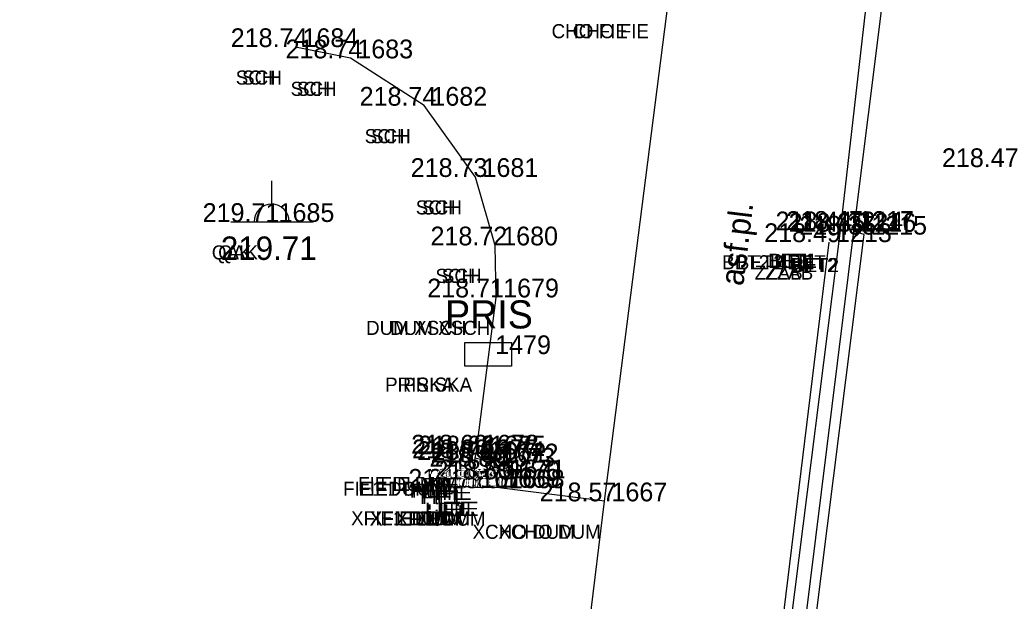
# Model space of a CAD drawing. Extents: x -471047 to -470889, y -1102859 to -1102000.
# Drawn here: x -470984.24 to -470963.12, y -1102410.26 to -1102397.86 of the extents above; entities that cross this region are included whole.
import ezdxf

# ---------------------------------------------------------------- set-up
doc = ezdxf.new("R2010")
doc.units = 0
for name, color, linetype in [('Vrstva 1', 7, 'Continuous'), ('Vrstva 10', 7, 'Continuous'), ('Vrstva 13', 7, 'Continuous'), ('Vrstva 17', 7, 'Continuous'), ('Vrstva 2', 7, 'Continuous'), ('Vrstva 22', 7, 'Continuous'), ('Vrstva 23', 7, 'Continuous'), ('Vrstva 34', 7, 'Continuous'), ('Vrstva 35', 7, 'Continuous'), ('Vrstva 36', 7, 'Continuous'), ('Vrstva 38', 7, 'Continuous'), ('Vrstva 5', 7, 'Continuous'), ('Vrstva 7', 7, 'Continuous'), ('Vrstva 8', 7, 'Continuous')]:
    doc.layers.add(name, color=color, linetype=linetype)

msp = doc.modelspace()

# ---------------------------------------------------------------- linework, layer by layer
at = {"layer": 'Vrstva 1'}
for points in [[(-471040.344, -1102858.385), (-471031.676, -1102846.187), (-471026.357, -1102838.629), (-471023.212, -1102833.975), (-471019.21, -1102827.465), (-471016.861, -1102823.272), (-471013.099, -1102815.912), (-471010.824, -1102810.955), (-471007.329, -1102802.292), (-471005.34, -1102796.515), (-471002.842, -1102787.838), (-471001.3, -1102780.997), (-471000.19, -1102774.713), (-470999.247, -1102768.204), (-470998.794, -1102764.784), (-470997.199, -1102751.812), (-470994.899, -1102732.807), (-470992.551, -1102713.262), (-470990.326, -1102694.887), (-470988.122, -1102676.57), (-470985.812, -1102657.305), (-470983.537, -1102638.407), (-470981.386, -1102620.622), (-470979.843, -1102608.014), (-470976.377, -1102579.253), (-470972.945, -1102550.69), (-470970.475, -1102530.206), (-470967.905, -1102508.801), (-470965.053, -1102485.131), (-470962.734, -1102465.9), (-470960.173, -1102444.812), (-470957.795, -1102425.103), (-470954.965, -1102401.839), (-470953.834, -1102392.574), (-470952.33, -1102379.985), (-470950.744, -1102366.853), (-470948.978, -1102352.106), (-470947.037, -1102335.844), (-470944.949, -1102318.462), (-470944.013, -1102310.745), (-470942.39, -1102297.267), (-470939.519, -1102273.45), (-470937.593, -1102257.43), (-470936.064, -1102244.81), (-470934.114, -1102228.634), (-470931.621, -1102207.856), (-470929.536, -1102190.857), (-470926.572, -1102166.31), (-470924.91, -1102152.663), (-470923.413, -1102140.333), (-470921.923, -1102127.669), (-470921.155, -1102120.084), (-470920.446, -1102109.574), (-470919.912, -1102099.137), (-470919.63, -1102088.981), (-470919.523, -1102081.193), (-470919.563, -1102070.395), (-470919.714, -1102064.236), (-470920.134, -1102054.704), (-470920.462, -1102047.615), (-470920.599, -1102044.52), (-470920.743, -1102041.873), (-470921.125, -1102034.455), (-470921.774, -1102030.337), (-470922.418, -1102027.787), (-470923.734, -1102023.93), (-470924.872, -1102021.434), (-470926.752, -1102018.182), (-470927.953, -1102016.45), (-470929.616, -1102014.424), (-470932.252, -1102011.756), (-470935.111, -1102009.425), (-470938.391, -1102007.371), (-470942.651, -1102005.401)], [(-471041.328, -1102857.18), (-471032.144, -1102844.242), (-471027.583, -1102837.763), (-471024.388, -1102833.028), (-471020.451, -1102826.6), (-471018.089, -1102822.378), (-471014.542, -1102815.445), (-471012.233, -1102810.418), (-471009.247, -1102803.108), (-471006.795, -1102796.098), (-471004.315, -1102787.532), (-471002.782, -1102780.723), (-471001.674, -1102774.458), (-471000.75, -1102768.095), (-471000.28, -1102764.601), (-470998.692, -1102751.741), (-470996.378, -1102732.635), (-470994.028, -1102713.058), (-470991.808, -1102694.749), (-470989.616, -1102676.447), (-470987.284, -1102657.013), (-470985.031, -1102638.272), (-470982.87, -1102620.431), (-470981.334, -1102607.933), (-470977.881, -1102579.263), (-470974.429, -1102550.492), (-470971.964, -1102530.054), (-470969.391, -1102508.607), (-470966.54, -1102484.984), (-470964.231, -1102465.853), (-470961.679, -1102444.752), (-470959.304, -1102425.078), (-470956.455, -1102401.634), (-470955.339, -1102392.489), (-470953.812, -1102379.71), (-470952.249, -1102366.808), (-470950.479, -1102352.023), (-470948.536, -1102335.868), (-470946.426, -1102318.233), (-470945.493, -1102310.531), (-470943.864, -1102297.013), (-470940.984, -1102273.071), (-470939.078, -1102257.195), (-470937.559, -1102244.684), (-470935.592, -1102228.353), (-470933.101, -1102207.653), (-470931.011, -1102190.57), (-470928.046, -1102166.021), (-470926.409, -1102152.578), (-470924.898, -1102140.121), (-470923.427, -1102127.544), (-470922.647, -1102119.826), (-470921.919, -1102109.229), (-470921.42, -1102099.134), (-470921.127, -1102089.016), (-470921.023, -1102081.453), (-470921.061, -1102070.468), (-470921.209, -1102064.314), (-470921.666, -1102053.966), (-470922.156, -1102043.345), (-470922.299, -1102039.934), (-470922.637, -1102034.36), (-470923.091, -1102031.241), (-470923.847, -1102028.247), (-470925.083, -1102024.594), (-470926.222, -1102022.086), (-470928.04, -1102018.943), (-470929.138, -1102017.357), (-470930.929, -1102015.175), (-470933.062, -1102013.049), (-470936.379, -1102010.368), (-470939.169, -1102008.662), (-470942.899, -1102006.906), (-470945.661, -1102005.908)], [(-471043.557, -1102855.955), (-471035.129, -1102844.026), (-471029.872, -1102836.499), (-471026.577, -1102831.578), (-471022.675, -1102825.415), (-471020.123, -1102821.053), (-471016.667, -1102814.59), (-471014.208, -1102809.45), (-471011.177, -1102802.451), (-471008.55, -1102795.333), (-471006.082, -1102787.209), (-471004.464, -1102780.376), (-471003.265, -1102774.167), (-471002.327, -1102767.948), (-471001.636, -1102762.527), (-471000.297, -1102751.605), (-470997.959, -1102732.524), (-470995.602, -1102712.802), (-470993.412, -1102694.623), (-470991.21, -1102676.17), (-470988.891, -1102656.857), (-470986.625, -1102638.083), (-470984.455, -1102620.195), (-470982.936, -1102607.733), (-470979.497, -1102579.223), (-470976.023, -1102550.279), (-470973.554, -1102529.822), (-470970.991, -1102508.497), (-470968.146, -1102484.787), (-470965.835, -1102465.72), (-470963.284, -1102444.529), (-470960.91, -1102424.942), (-470958.043, -1102401.343), (-470956.946, -1102392.356), (-470955.396, -1102379.408), (-470953.851, -1102366.636), (-470952.049, -1102351.733), (-470950.124, -1102335.611), (-470948.034, -1102318.083), (-470947.094, -1102310.328), (-470945.421, -1102296.51), (-470942.58, -1102272.848), (-470940.675, -1102256.948), (-470939.176, -1102244.526), (-470937.187, -1102228.174), (-470934.708, -1102207.467), (-470932.621, -1102190.433), (-470929.634, -1102165.778), (-470928.004, -1102152.415), (-470926.45, -1102139.595), (-470925.003, -1102127.418), (-470924.249, -1102119.695), (-470923.515, -1102109.093), (-470923.018, -1102099.069), (-470922.711, -1102088.911), (-470922.643, -1102081.356), (-470922.797, -1102070.414), (-470923.018, -1102064.454), (-470923.52, -1102053.203), (-470923.823, -1102047.529), (-470924.123, -1102041.506), (-470924.462, -1102037.486), (-470924.934, -1102031.904), (-470925.664, -1102028.672), (-470926.771, -1102025.506), (-470927.959, -1102022.914), (-470929.674, -1102020.028), (-470930.76, -1102018.498), (-470932.447, -1102016.478), (-470935.215, -1102013.816), (-470937.644, -1102011.98), (-470940.381, -1102010.371), (-470943.968, -1102008.669), (-470947.145, -1102007.524), (-470950.874, -1102006.74)], [(-471044.756, -1102855.056), (-471036.376, -1102843.177), (-471031.167, -1102835.741), (-471027.859, -1102830.8), (-471023.934, -1102824.593), (-471021.43, -1102820.312), (-471018.011, -1102813.91), (-471015.536, -1102808.75), (-471012.578, -1102801.897), (-471009.95, -1102794.77), (-471007.561, -1102786.914), (-471005.936, -1102780.074), (-471004.727, -1102773.818), (-471003.828, -1102767.827), (-471003.121, -1102762.345), (-471001.787, -1102751.467), (-470999.446, -1102732.348), (-470997.073, -1102712.539), (-470994.902, -1102694.521), (-470992.696, -1102676.023), (-470990.376, -1102656.68), (-470988.131, -1102638.071), (-470985.947, -1102620.018), (-470984.417, -1102607.512), (-470980.993, -1102579.08), (-470977.514, -1102550.137), (-470975.048, -1102529.649), (-470972.488, -1102508.37), (-470969.618, -1102484.508), (-470967.34, -1102465.669), (-470964.767, -1102444.39), (-470962.402, -1102424.781), (-470959.534, -1102401.193), (-470958.432, -1102392.151), (-470956.883, -1102379.208), (-470955.335, -1102366.424), (-470953.535, -1102351.506), (-470951.606, -1102335.399), (-470949.519, -1102317.94), (-470948.575, -1102310.159), (-470946.889, -1102296.144), (-470944.056, -1102272.618), (-470942.139, -1102256.659), (-470940.657, -1102244.341), (-470938.638, -1102227.749), (-470936.19, -1102207.298), (-470934.102, -1102190.255), (-470931.124, -1102165.639), (-470929.492, -1102152.254), (-470927.915, -1102139.252), (-470926.46, -1102127.103), (-470925.74, -1102119.604), (-470925.012, -1102108.913), (-470924.523, -1102099.054), (-470924.217, -1102088.866), (-470924.148, -1102081.334), (-470924.301, -1102070.391), (-470924.518, -1102064.43), (-470924.97, -1102054.435), (-470925.588, -1102041.569), (-470925.963, -1102035.313), (-470926.405, -1102032.225), (-470927.078, -1102029.198), (-470928.123, -1102026.148), (-470929.318, -1102023.558), (-470930.84, -1102020.97), (-470931.868, -1102019.515), (-470933.443, -1102017.605), (-470936.26, -1102014.885), (-470938.429, -1102013.255), (-470941.213, -1102011.639), (-470944.847, -1102009.927), (-470947.723, -1102008.912), (-470951.444, -1102008.161), (-470954.511, -1102007.931), (-470957.895, -1102008.041)]]:
    msp.add_spline(points, degree=3, dxfattribs=at)
at = {"layer": 'Vrstva 10'}
for p, q in [((-470974.508, -1102407.105), (-470974.083, -1102403.784)), ((-470974.568, -1102407.837), (-470974.525, -1102407.212)), ((-470974.525, -1102407.212), (-470974.508, -1102407.105)), ((-470974.062, -1102407.837), (-470974.568, -1102407.837)), ((-470973.962, -1102407.851), (-470974.062, -1102407.837)), ((-470971.771, -1102408.129), (-470973.962, -1102407.851)), ((-470972.725, -1102415.976), (-470971.771, -1102408.129))]:
    msp.add_line(p, q, dxfattribs=at)
at = {"layer": 'Vrstva 13'}
for p, q in [((-470978.867, -1102401.792), (-470978.867, -1102401.292)), ((-470978.867, -1102401.792), (-470978.867, -1102402.167)), ((-470978.867, -1102401.817), (-470978.867, -1102401.817)), ((-470979.742, -1102402.167), (-470977.992, -1102402.167)), ((-470978.867, -1102402.167), (-470978.492, -1102402.167))]:
    msp.add_line(p, q, dxfattribs=at)
for start, end in [(90, 180), (0, 90)]:
    msp.add_arc((-470978.867, -1102402.167), 0.375, start, end, dxfattribs=at)
at = {"layer": 'Vrstva 17'}
for p, q in [((-470977.188, -1102398.675), (-470978.361, -1102398.439)), ((-470975.613, -1102399.685), (-470977.188, -1102398.675)), ((-470974.524, -1102401.212), (-470975.613, -1102399.685)), ((-470974.101, -1102402.672), (-470974.524, -1102401.212)), ((-470974.083, -1102403.784), (-470974.101, -1102402.672))]:
    msp.add_line(p, q, dxfattribs=at)
at = {"layer": 'Vrstva 2'}
msp.add_line((-470968.697, -1102416.63), (-470966.978, -1102402.603), dxfattribs=at)
at = {"layer": 'Vrstva 23'}
msp.add_lwpolyline([(-470974.75, -1102404.744), (-470973.75, -1102404.744), (-470973.75, -1102405.244), (-470974.75, -1102405.244)], close=True, dxfattribs=at)
at = {"layer": 'Vrstva 34'}
for p, q in [((-470978.36, -1102398.44), (-470978.36, -1102398.44)), ((-470977.19, -1102398.68), (-470977.19, -1102398.68)), ((-470975.61, -1102399.69), (-470975.61, -1102399.69)), ((-470963.19, -1102401), (-470963.19, -1102401)), ((-470974.52, -1102401.21), (-470974.52, -1102401.21)), ((-470978.87, -1102402.17), (-470978.87, -1102402.17)), ((-470966.74, -1102402.35), (-470966.74, -1102402.35)), ((-470966.51, -1102402.34), (-470966.51, -1102402.34)), ((-470966.46, -1102402.38), (-470966.46, -1102402.38)), ((-470966.98, -1102402.6), (-470966.98, -1102402.6)), ((-470966.23, -1102402.44), (-470966.23, -1102402.44)), ((-470974.1, -1102402.67), (-470974.1, -1102402.67)), ((-470974.08, -1102403.78), (-470974.08, -1102403.78)), ((-470974.25, -1102404.99), (-470974.25, -1102404.99)), ((-470974.53, -1102407.21), (-470974.53, -1102407.21)), ((-470974.51, -1102407.11), (-470974.51, -1102407.11)), ((-470974.38, -1102407.25), (-470974.38, -1102407.25)), ((-470974.36, -1102407.13), (-470974.36, -1102407.13)), ((-470974.16, -1102407.39), (-470974.16, -1102407.39)), ((-470974.09, -1102407.3), (-470974.09, -1102407.3)), ((-470974.05, -1102407.66), (-470974.05, -1102407.66)), ((-470973.94, -1102407.64), (-470973.94, -1102407.64)), ((-470974.57, -1102407.84), (-470974.57, -1102407.84)), ((-470974.06, -1102407.84), (-470974.06, -1102407.84)), ((-470973.96, -1102407.85), (-470973.96, -1102407.85)), ((-470971.77, -1102408.13), (-470971.77, -1102408.13))]:
    msp.add_line(p, q, dxfattribs=at)
at = {"layer": 'Vrstva 5'}
for p, q in [((-470966.23, -1102402.435), (-470966.455, -1102402.375)), ((-470967.997, -1102416.48), (-470966.23, -1102402.435))]:
    msp.add_line(p, q, dxfattribs=at)
at = {"layer": 'Vrstva 7'}
for p, q in [((-470966.74, -1102402.353), (-470966.113, -1102396.933)), ((-470968.535, -1102416.572), (-470966.74, -1102402.353)), ((-470974.382, -1102407.246), (-470974.525, -1102407.212)), ((-470974.158, -1102407.385), (-470974.382, -1102407.246)), ((-470974.052, -1102407.657), (-470974.158, -1102407.385)), ((-470974.062, -1102407.837), (-470974.052, -1102407.657))]:
    msp.add_line(p, q, dxfattribs=at)
at = {"layer": 'Vrstva 8'}
for p, q in [((-470966.455, -1102402.375), (-470965.779, -1102396.97)), ((-470971.771, -1102408.129), (-470970.407, -1102397.445)), ((-470968.204, -1102416.536), (-470966.455, -1102402.375)), ((-470974.356, -1102407.126), (-470974.508, -1102407.105)), ((-470974.089, -1102407.297), (-470974.356, -1102407.126)), ((-470973.944, -1102407.641), (-470974.089, -1102407.297)), ((-470973.962, -1102407.851), (-470973.944, -1102407.641))]:
    msp.add_line(p, q, dxfattribs=at)

# ---------------------------------------------------------------- texts
at = {"layer": 'Vrstva 22'}
msp.add_text('asf.pl.', height=0.5, rotation=83.0293, dxfattribs=at).set_placement((-470968.811, -1102403.548))
msp.add_text('219.71', height=0.5, dxfattribs=at).set_placement((-470979.953, -1102402.98))
at = {"layer": 'Vrstva 23'}
msp.add_text('PRIS', height=0.6, dxfattribs=at).set_placement((-470975.17, -1102404.442))
at = {"layer": 'Vrstva 35'}
for s, p in [('CHO FIE', (-470972.898, -1102398.25)), ('CHO FIE', (-470972.449, -1102398.25)), ('SCH', (-470979.635, -1102399.24)), ('SCH', (-470979.499, -1102399.24)), ('SCH', (-470978.465, -1102399.48)), ('SCH', (-470978.329, -1102399.48)), ('SCH', (-470976.885, -1102400.49)), ('SCH', (-470976.749, -1102400.49)), ('SCH', (-470975.795, -1102402.01)), ('SCH', (-470975.659, -1102402.01)), ('QAK', (-470980.145, -1102402.97)), ('QAK', (-470980.009, -1102402.97)), ('BET2 BET', (-470969.26, -1102403.18)), ('BET2 BET', (-470968.949, -1102403.18)), ('BET1', (-470968.282, -1102403.15)), ('BET1', (-470968.24, -1102403.15)), ('BET2', (-470967.805, -1102403.24)), ('BET2', (-470967.771, -1102403.24)), ('SCH', (-470975.375, -1102403.47)), ('SCH', (-470975.239, -1102403.47)), ('ZZAB', (-470968.569, -1102403.4)), ('ZZAB', (-470968.344, -1102403.4)), ('DUM XSCH', (-470976.855, -1102404.58)), ('DUM XSCH', (-470976.344, -1102404.58)), ('PRISKA', (-470976.45, -1102405.79)), ('PRISKA', (-470976.064, -1102405.79)), ('FIE DUM', (-470977.025, -1102407.91)), ('FIE DUM', (-470976.549, -1102407.91)), ('FIE', (-470975.648, -1102407.93)), ('FIE', (-470975.499, -1102407.93)), ('FIE1 DUM', (-470977.345, -1102408.01)), ('FIE1 DUM', (-470977.019, -1102408.01)), ('FIE1', (-470975.922, -1102408.05)), ('FIE1', (-470975.88, -1102408.05)), ('FIE1', (-470975.702, -1102408.19)), ('FIE1', (-470975.66, -1102408.19)), ('FIE', (-470975.378, -1102408.1)), ('FIE', (-470975.229, -1102408.1)), ('XFIE1 DUM', (-470977.175, -1102408.64)), ('XFIE1 DUM', (-470976.775, -1102408.64)), ('DUM', (-470975.885, -1102408.64)), ('DUM', (-470975.709, -1102408.64)), ('FIE1', (-470975.592, -1102408.46)), ('FIE1', (-470975.55, -1102408.46)), ('FIE', (-470975.228, -1102408.44)), ('FIE', (-470975.079, -1102408.44)), ('XFIE DUM', (-470976.775, -1102408.65)), ('XFIE DUM', (-470976.224, -1102408.65)), ('XCHO DUM', (-470974.585, -1102408.93)), ('XCHO DUM', (-470974.034, -1102408.93))]:
    msp.add_text(s, height=0.3, dxfattribs=at).set_placement(p)
at = {"layer": 'Vrstva 36'}
for s, p in [(' 1684', (-470978.36, -1102398.44)), (' 1683', (-470977.19, -1102398.68)), (' 1682', (-470975.61, -1102399.69)), (' 1681', (-470974.52, -1102401.21)), (' 1685', (-470978.87, -1102402.17)), (' 1214', (-470966.74, -1102402.35)), (' 1217', (-470966.51, -1102402.34)), (' 1216', (-470966.46, -1102402.38)), (' 1213', (-470966.98, -1102402.6)), (' 1215', (-470966.23, -1102402.44)), (' 1680', (-470974.1, -1102402.67)), (' 1679', (-470974.08, -1102403.78)), (' 1479', (-470974.25, -1102404.99)), (' 1677', (-470974.53, -1102407.21)), (' 1678', (-470974.51, -1102407.11)), (' 1674', (-470974.38, -1102407.25)), (' 1675', (-470974.36, -1102407.13)), (' 1673', (-470974.16, -1102407.39)), (' 1672', (-470974.09, -1102407.3)), (' 1670', (-470974.05, -1102407.66)), (' 1671', (-470973.94, -1102407.64)), (' 1676', (-470974.57, -1102407.84)), (' 1669', (-470974.06, -1102407.84)), (' 1668', (-470973.96, -1102407.85)), (' 1667', (-470971.77, -1102408.13))]:
    msp.add_text(s, height=0.4, dxfattribs=at).set_placement(p)
at = {"layer": 'Vrstva 38'}
for s, p in [('218.74 ', (-470979.742, -1102398.44)), ('218.74 ', (-470978.572, -1102398.68)), ('218.74 ', (-470976.992, -1102399.69)), ('218.47 ', (-470964.573, -1102401)), ('218.73 ', (-470975.903, -1102401.21)), ('219.71 ', (-470980.34, -1102402.17)), ('218.44 ', (-470968.122, -1102402.35)), ('218.47 ', (-470967.893, -1102402.34)), ('218.35 ', (-470967.844, -1102402.38)), ('218.49 ', (-470968.364, -1102402.6)), ('218.35 ', (-470967.614, -1102402.44)), ('218.72 ', (-470975.481, -1102402.67)), ('218.71 ', (-470975.55, -1102403.78)), ('218.69 ', (-470975.894, -1102407.11)), ('218.80 ', (-470975.873, -1102407.21)), ('218.79 ', (-470975.764, -1102407.25)), ('218.68 ', (-470975.744, -1102407.13)), ('218.80 ', (-470975.503, -1102407.39)), ('218.67 ', (-470975.473, -1102407.3)), ('218.80 ', (-470975.393, -1102407.66)), ('218.66 ', (-470975.3, -1102407.64)), ('218.77 ', (-470975.953, -1102407.84)), ('218.81 ', (-470975.53, -1102407.84)), ('218.67 ', (-470975.343, -1102407.85)), ('218.57 ', (-470973.153, -1102408.13))]:
    msp.add_text(s, height=0.4, dxfattribs=at).set_placement(p)

doc.saveas('drawing.dxf')
